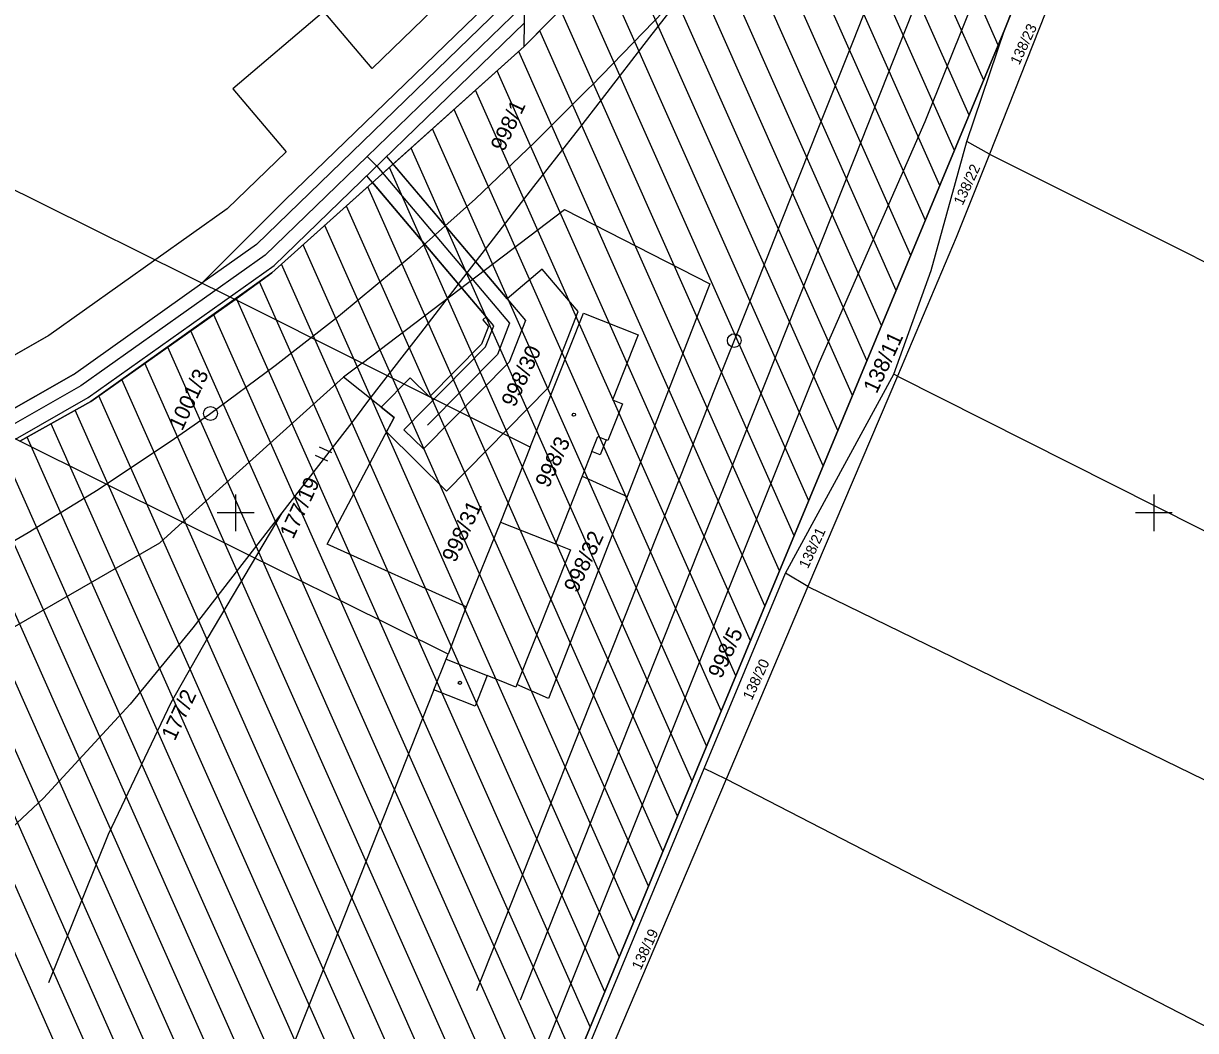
# Model space of a CAD drawing. Extents: x -755061 to -754557, y -1162352 to -1161657.
# Drawn here: x -754923.1 to -754795.5, y -1162256.4 to -1162146.7 of the extents above; entities that cross this region are included whole.
import ezdxf

# ---------------------------------------------------------------- set-up
doc = ezdxf.new("R2010")
doc.units = 0
for name, color, linetype in [('ADJ_Síť', 7, 'Continuous'), ('DTA-TZ', 7, 'Continuous'), ('DTA_DZ_DO_hranice', 7, 'Continuous'), ('DTA_DZ_DO_ostatní', 7, 'Continuous'), ('DTA_DZ_DO_ZPF', 7, 'Continuous'), ('DTA_ochranné pásmo', 7, 'Continuous'), ('DTA_projektovaný_stav', 7, 'Continuous'), ('DTA_správa_investora', 7, 'Continuous'), ('KN_Katastrální hranice', 7, 'Continuous'), ('KN_Vrstva 55', 7, 'Continuous'), ('KN_Vrstva 56', 7, 'Continuous'), ('KN_Vrstva 57', 7, 'Continuous'), ('KN_Vrstva 58', 7, 'Continuous'), ('KN_Vrstva 59', 7, 'Continuous'), ('Staniceni a namezniky', 7, 'Continuous'), ('Vrstva 1', 7, 'Continuous'), ('Vrstva 53', 7, 'Continuous')]:
    doc.layers.add(name, color=color, linetype=linetype)

msp = doc.modelspace()

# ---------------------------------------------------------------- linework, layer by layer
at = {"layer": 'ADJ_Síť'}
for points in [[(-754900, -1162198), (-754900, -1162200), (-754900, -1162202)], [(-754900, -1162198), (-754900, -1162200), (-754900, -1162202)], [(-754800, -1162198), (-754800, -1162200), (-754800, -1162202)], [(-754800, -1162198), (-754800, -1162200), (-754800, -1162202)], [(-754898, -1162200), (-754900, -1162200), (-754902, -1162200)], [(-754898, -1162200), (-754900, -1162200), (-754902, -1162200)], [(-754798, -1162200), (-754800, -1162200), (-754802, -1162200)], [(-754798, -1162200), (-754800, -1162200), (-754802, -1162200)]]:
    msp.add_lwpolyline(points, dxfattribs=at)
at = {"layer": 'DTA-TZ'}
msp.add_lwpolyline([(-754923.5, -1162192.2), (-754927.24, -1162190.37), (-754917.66, -1162184.92), (-754903.67, -1162174.98), (-754894.6, -1162165.92), (-754868.47, -1162140.62), (-754868.42, -1162135.23), (-754861.18, -1162138.93), (-754862.16, -1162142.69), (-754868.56, -1162149.23), (-754896.07, -1162173.88), (-754915.78, -1162187.87), (-754923.5, -1162192.2)], dxfattribs=at)
at = {"layer": 'DTA_DZ_DO_hranice'}
for points in [[(-754882.86, -1162162.04), (-754868.56, -1162149.23), (-754862.16, -1162142.69), (-754850.97, -1162130.01), (-754843.96, -1162120.41), (-754829.74, -1162126.8), (-754821.22, -1162106.53), (-754831.28, -1162101.48), (-754823.58, -1162088.63), (-754816.76, -1162075.96)], [(-754868.42, -1162135.23), (-754868.42, -1162135.42), (-754885.14, -1162151.61), (-754890.41, -1162145.41), (-754900.32, -1162153.82), (-754894.5, -1162160.68), (-754900.94, -1162166.91), (-754920.36, -1162180.69), (-754945.08, -1162194.78)], [(-754923.5, -1162192.2), (-754915.78, -1162187.87), (-754896.07, -1162173.88), (-754885.09, -1162164.04), (-754872.71, -1162178.65), (-754873.09, -1162178.98), (-754872.46, -1162179.71), (-754873.21, -1162181.63), (-754878.88, -1162187.38), (-754881.01, -1162185.28), (-754884.16, -1162188.47), (-754882.73, -1162189.61), (-754883.56, -1162191.19), (-754877.03, -1162197.62), (-754865.92, -1162186.35), (-754862.71, -1162178.08), (-754866.6, -1162173.48), (-754870.42, -1162176.71), (-754882.86, -1162162.04)]]:
    msp.add_lwpolyline(points, dxfattribs=at)
at = {"layer": 'DTA_DZ_DO_ostatní'}
msp.add_lwpolyline([(-754882.86, -1162162.04), (-754885.09, -1162164.04), (-754872.71, -1162178.65), (-754873.09, -1162178.98), (-754872.46, -1162179.71), (-754873.21, -1162181.63), (-754878.88, -1162187.38), (-754881.01, -1162185.28), (-754884.16, -1162188.47), (-754882.73, -1162189.61), (-754883.56, -1162191.19), (-754877.03, -1162197.62), (-754865.92, -1162186.35), (-754862.71, -1162178.08), (-754866.6, -1162173.48), (-754870.42, -1162176.71)], close=True, dxfattribs=at)
at = {"layer": 'DTA_DZ_DO_ZPF'}
msp.add_lwpolyline([(-754927.24, -1162190.37), (-754917.66, -1162184.92), (-754903.67, -1162174.98), (-754894.6, -1162165.92), (-754868.47, -1162140.62), (-754868.42, -1162135.42), (-754885.14, -1162151.61), (-754890.41, -1162145.41), (-754900.32, -1162153.82), (-754894.5, -1162160.68), (-754900.94, -1162166.91), (-754920.36, -1162180.69), (-754932.68, -1162187.72)], dxfattribs=at)
at = {"layer": 'DTA_ochranné pásmo'}
for p, q in [((-754868.49, -1162142.45), (-754897.74, -1162170.77)), ((-754895.81, -1162173.08), (-754868.53, -1162146.66)), ((-754897.74, -1162170.77), (-754903.67, -1162174.98)), ((-754916.05, -1162187.45), (-754895.81, -1162173.08)), ((-754917.66, -1162184.92), (-754903.67, -1162174.98)), ((-754917.66, -1162184.92), (-754927.24, -1162190.37)), ((-754917.66, -1162184.92), (-754917.66, -1162184.92)), ((-754923.98, -1162191.97), (-754916.05, -1162187.45))]:
    msp.add_line(p, q, dxfattribs=at)
msp.add_lwpolyline([(-754883.56, -1162161.21), (-754868.45, -1162179.04), (-754870.21, -1162183.57), (-754879.54, -1162193.04), (-754881.68, -1162190.94), (-754872.78, -1162181.91), (-754871.89, -1162179.62), (-754885.72, -1162163.3)], dxfattribs=at)
at = {"layer": 'DTA_projektovaný_stav'}
for points in [[(-754758.34, -1161933.06), (-754762.34, -1161937.68), (-754763.29, -1161936.85), (-754776.47, -1161949.62), (-754777.37, -1161978.41), (-754796.3, -1162026.28), (-754809.87, -1162057.58), (-754831.07, -1162091.65), (-754857.54, -1162133.93), (-754885.68, -1162161.18), (-754896.77, -1162171.93), (-754916.86, -1162186.18), (-754942.05, -1162200.54), (-754965.03, -1162211.64), (-754990.89, -1162220.78), (-755014.11, -1162227.27), (-755008.76, -1162253.14), (-755005.05, -1162256.17)], [(-754885.68, -1162161.18), (-754884.64, -1162162.26), (-754870.17, -1162179.33), (-754871.49, -1162182.74), (-754879.1, -1162190.46)]]:
    msp.add_lwpolyline(points, dxfattribs=at)
at = {"layer": 'DTA_správa_investora'}
for p, q in [((-754816.94, -1162149.08), (-754842.99, -1162090.44)), ((-754818.53, -1162152.9), (-754844.99, -1162093.32)), ((-754820.12, -1162156.71), (-754847, -1162096.19)), ((-754821.71, -1162160.53), (-754849, -1162099.07)), ((-754823.29, -1162164.34), (-754851.01, -1162101.94)), ((-754824.88, -1162168.15), (-754853.02, -1162104.82)), ((-754826.47, -1162171.97), (-754854.99, -1162107.76)), ((-754828.06, -1162175.78), (-754856.8, -1162111.07)), ((-754829.65, -1162179.6), (-754858.62, -1162114.36)), ((-754831.24, -1162183.41), (-754860.49, -1162117.55)), ((-754832.82, -1162187.23), (-754862.36, -1162120.73)), ((-754834.41, -1162191.04), (-754864.23, -1162123.91)), ((-754836, -1162194.86), (-754866.03, -1162127.25)), ((-754837.59, -1162198.67), (-754862.36, -1162142.9)), ((-754839.18, -1162202.48), (-754864.62, -1162145.2)), ((-754840.77, -1162206.3), (-754866.88, -1162147.51)), ((-754842.35, -1162210.11), (-754869.16, -1162149.77)), ((-754843.94, -1162213.93), (-754871.51, -1162151.87)), ((-754845.53, -1162217.74), (-754873.86, -1162153.97)), ((-754847.12, -1162221.56), (-754876.2, -1162156.08)), ((-754848.71, -1162225.37), (-754878.55, -1162158.18)), ((-754850.29, -1162229.19), (-754880.9, -1162160.29)), ((-754851.88, -1162233), (-754883.25, -1162162.39)), ((-754853.47, -1162236.83), (-754885.6, -1162164.49)), ((-754855.05, -1162240.65), (-754887.94, -1162166.6)), ((-754856.63, -1162244.48), (-754890.29, -1162168.7)), ((-754858.22, -1162248.3), (-754892.64, -1162170.81)), ((-754859.8, -1162252.13), (-754894.99, -1162172.91)), ((-754861.38, -1162255.95), (-754897.41, -1162174.85)), ((-754862.97, -1162259.78), (-754899.89, -1162176.65)), ((-754864.55, -1162263.6), (-754902.39, -1162178.42)), ((-754866.14, -1162267.42), (-754904.89, -1162180.18)), ((-754867.72, -1162271.25), (-754907.39, -1162181.94)), ((-754869.3, -1162275.07), (-754909.89, -1162183.71)), ((-754870.89, -1162278.9), (-754912.39, -1162185.47)), ((-754872.47, -1162282.72), (-754914.89, -1162187.24)), ((-754874.06, -1162286.55), (-754917.47, -1162188.82)), ((-754875.64, -1162290.37), (-754920.09, -1162190.29)), ((-754877.22, -1162294.2), (-754922.72, -1162191.76)), ((-754878.81, -1162298.02), (-754925.34, -1162193.26)), ((-754880.39, -1162301.85), (-754927.96, -1162194.76)), ((-754881.97, -1162305.67), (-754930.57, -1162196.26)), ((-754883.56, -1162309.49), (-754933.19, -1162197.76)), ((-754885.62, -1162312.24), (-754935.81, -1162199.26)), ((-754889.58, -1162310.72), (-754938.42, -1162200.76)), ((-754893.54, -1162309.19), (-754941.04, -1162202.26)), ((-754897.5, -1162307.67), (-754943.74, -1162203.57))]:
    msp.add_line(p, q, dxfattribs=at)
for points in [[(-755057.07, -1162235.3), (-755060.75, -1162244.84), (-754884.82, -1162312.55), (-754851.45, -1162231.96), (-754816.22, -1162147.35), (-754802.96, -1162113.9), (-754798.15, -1162101.07), (-754793.13, -1162087.4), (-754789, -1162076.26), (-754760.29, -1162004.33), (-754756.33, -1161996.85), (-754754.27, -1161988.55), (-754747.84, -1161978.77), (-754745.89, -1161978.47), (-754750.32, -1161972.64), (-754749.74, -1161970.12), (-754747.41, -1161959.83), (-754731.42, -1161979.09), (-754717.5, -1161955.11), (-754704.12, -1161932.06), (-754747.69, -1161915.3)], [(-754812.88, -1162068.75), (-754816.76, -1162075.96), (-754822.47, -1162073.13), (-754828.75, -1162070.02), (-754837.06, -1162081.94), (-754854.71, -1162107.25), (-754858.37, -1162113.93), (-754865.75, -1162126.5), (-754868.4, -1162133.56), (-754868.42, -1162135.23), (-754861.18, -1162138.93), (-754862.16, -1162142.69), (-754868.56, -1162149.23), (-754896.07, -1162173.88), (-754900.06, -1162176.77), (-754915.78, -1162187.87), (-754923.5, -1162192.2)]]:
    msp.add_lwpolyline(points, dxfattribs=at)
at = {"layer": 'KN_Katastrální hranice'}
msp.add_line((-754811.54, -1162135.54), (-754816.22, -1162147.35), dxfattribs=at)
msp.add_lwpolyline([(-754816.22, -1162147.35), (-754851.45, -1162231.96), (-754884.82, -1162312.55)], dxfattribs=at)
at = {"layer": 'KN_Vrstva 55'}
for p, q in [((-755012.97, -1162120.69), (-754900.06, -1162176.77)), ((-754868.56, -1162149.23), (-754868.42, -1162135.23)), ((-754811.54, -1162135.54), (-754816.22, -1162147.35)), ((-754811.54, -1162135.54), (-754816.22, -1162147.35)), ((-754808.43, -1162137.05), (-754817.91, -1162160.94)), ((-754868.56, -1162149.23), (-754862.16, -1162142.69)), ((-754820.38, -1162159.55), (-754816.22, -1162147.35)), ((-754817.91, -1162160.94), (-754820.38, -1162159.55)), ((-754886.23, -1162183.69), (-754864.19, -1162166.97)), ((-754886.23, -1162183.69), (-754900.06, -1162176.77)), ((-754886.23, -1162183.69), (-754888.26, -1162185.23)), ((-754867.91, -1162192.86), (-754886.23, -1162183.69)), ((-754888.26, -1162185.23), (-754905.78, -1162201)), ((-754840.13, -1162206.56), (-754828.31, -1162184.9)), ((-754827.93, -1162185.11), (-754837.67, -1162208.02)), ((-754827.93, -1162185.11), (-754828.31, -1162184.9)), ((-754905.78, -1162201), (-754923.5, -1162192.2)), ((-754862.27, -1162196.01), (-754857.37, -1162198.21)), ((-754876.85, -1162215.37), (-754905.78, -1162201)), ((-754848.96, -1162227.81), (-754840.13, -1162206.56)), ((-754837.67, -1162208.02), (-754840.13, -1162206.56)), ((-754837.67, -1162208.02), (-754846.58, -1162228.99)), ((-754874.91, -1162210.24), (-754876.85, -1162215.37)), ((-754863.44, -1162262.66), (-754848.96, -1162227.81)), ((-754846.58, -1162228.99), (-754848.96, -1162227.81))]:
    msp.add_line(p, q, dxfattribs=at)
for points in [[(-754888.68, -1162311.07), (-754870.17, -1162267.96), (-754836.4, -1162183.6), (-754824.89, -1162157.4), (-754808.97, -1162117.64), (-754790.52, -1162068.93), (-754761.32, -1161999.17), (-754754.27, -1161988.55)], [(-754816.22, -1162147.35), (-754851.45, -1162231.96), (-754884.82, -1162312.55)], [(-754816.22, -1162147.35), (-754851.45, -1162231.96), (-754884.82, -1162312.55)], [(-754900.06, -1162176.77), (-754896.07, -1162173.88), (-754868.56, -1162149.23)], [(-754828.31, -1162184.9), (-754824.25, -1162173.6), (-754820.38, -1162159.55)], [(-754817.91, -1162160.94), (-754821.51, -1162170), (-754827.93, -1162185.11)], [(-754817.91, -1162160.94), (-754773.06, -1162183.36), (-754728.03, -1162207.21)], [(-754864.19, -1162166.97), (-754848.34, -1162175.05), (-754857.37, -1162198.21)], [(-754923.5, -1162192.2), (-754915.78, -1162187.87), (-754900.06, -1162176.77)], [(-754867.91, -1162192.86), (-754862.1, -1162178.26), (-754856.15, -1162180.61), (-754858.96, -1162187.7), (-754857.88, -1162188.11), (-754859.46, -1162192.12), (-754859.66, -1162192.04), (-754860.31, -1162193.68), (-754861.2, -1162193.33), (-754862.27, -1162196.01)], [(-754874.91, -1162210.24), (-754890.05, -1162203.42), (-754882.73, -1162189.61), (-754888.26, -1162185.23)], [(-754827.93, -1162185.11), (-754743.71, -1162227.55), (-754737.2, -1162231.03)], [(-754867.91, -1162192.86), (-754871.15, -1162201.02), (-754874.91, -1162210.24)], [(-754862.27, -1162196.01), (-754865.18, -1162203.36), (-754863.54, -1162204.02), (-754869.36, -1162218.68)], [(-754857.37, -1162198.21), (-754865.94, -1162220.19), (-754869.36, -1162218.68)], [(-754971.15, -1162234.1), (-754958.95, -1162230.19), (-754951.07, -1162227.67), (-754947.14, -1162225.65), (-754943.74, -1162223.69), (-754908.27, -1162203.24), (-754905.78, -1162201)], [(-754837.67, -1162208.02), (-754745.6, -1162252.88)], [(-754878.41, -1162219.27), (-754877.09, -1162215.93), (-754876.85, -1162215.37)], [(-754869.36, -1162218.68), (-754869.47, -1162218.96), (-754872.61, -1162217.71), (-754873.93, -1162221.05), (-754878.41, -1162219.27)], [(-754878.41, -1162219.27), (-754890.63, -1162250.1), (-754895.21, -1162261.65), (-754899.8, -1162273.21), (-754904.37, -1162284.73), (-754908.92, -1162296.21), (-754911.35, -1162302.34)], [(-754846.58, -1162228.99), (-754858.59, -1162257.23), (-754861.29, -1162263.76)], [(-754754.65, -1162276.39), (-754846.58, -1162228.99)]]:
    msp.add_lwpolyline(points, dxfattribs=at)
at = {"layer": 'KN_Vrstva 56'}
for p, q in [((-754861.2, -1162193.33), (-754860.55, -1162191.69)), ((-754860.55, -1162191.69), (-754859.66, -1162192.04)), ((-754871.15, -1162201.02), (-754865.18, -1162203.36)), ((-754877.09, -1162215.93), (-754872.61, -1162217.71))]:
    msp.add_line(p, q, dxfattribs=at)
at = {"layer": 'KN_Vrstva 58'}
for p, q in [((-754889.52, -1162193.47), (-754890.88, -1162192.84)), ((-754889.95, -1162194.38), (-754891.3, -1162193.74))]:
    msp.add_line(p, q, dxfattribs=at)
at = {"layer": 'KN_Vrstva 59'}
for centre in [(-754863.16, -1162189.31), (-754875.58, -1162218.5)]:
    msp.add_circle(centre, 0.175, dxfattribs=at)
at = {"layer": 'Staniceni a namezniky'}
for centre in [(-754845.69, -1162181.24), (-754902.74, -1162189.18)]:
    msp.add_circle(centre, 0.75, dxfattribs=at)
at = {"layer": 'Vrstva 1'}
msp.add_line((-754885.52, -1162187.72), (-754886.99, -1162189.7), dxfattribs=at)
for points in [[(-754802.82, -1162068.46), (-754807.01, -1162076.73), (-754811.35, -1162084.87), (-754815.39, -1162092.12), (-754818.66, -1162097.67), (-754820.65, -1162100.99), (-754825.85, -1162109.19), (-754831.64, -1162117.68), (-754836.49, -1162124.37), (-754839.8, -1162128.71), (-754840.46, -1162129.57), (-754840.79, -1162129.99), (-754847.19, -1162138.25), (-754849.01, -1162140.58), (-754849.98, -1162141.84), (-754854.92, -1162148.19), (-754860.18, -1162155.01)], [(-754855.13, -1162205.06), (-754851.41, -1162195.67), (-754847.87, -1162186.72), (-754844.23, -1162177.57), (-754840.47, -1162168.07), (-754836.48, -1162158.01), (-754832.72, -1162148.55), (-754829.03, -1162139.24), (-754824.91, -1162128.83), (-754821.22, -1162119.52), (-754818.37, -1162112.34), (-754814.26, -1162101.97), (-754810.6, -1162092.76), (-754806.3, -1162081.9), (-754802.77, -1162073.01), (-754801.21, -1162069.06)], [(-754832.58, -1162161.33), (-754823.38, -1162138.13), (-754814.09, -1162114.62)], [(-754839.8, -1162128.71), (-754840.46, -1162129.57), (-754840.79, -1162129.99), (-754847.19, -1162138.25), (-754849.01, -1162140.58), (-754849.98, -1162141.84), (-754861.22, -1162153.45), (-754861.54, -1162153.77), (-754867.4, -1162159.65), (-754873.88, -1162165.79), (-754880.89, -1162172.03), (-754888.58, -1162178.44), (-754889.11, -1162178.86), (-754895.68, -1162183.99), (-754902.86, -1162189.27), (-754906.67, -1162191.94), (-754914.99, -1162197.47), (-754922.58, -1162202.18), (-754930.39, -1162206.7)], [(-754860.18, -1162155.01), (-754862.55, -1162158.06), (-754867.55, -1162164.48), (-754872.3, -1162170.63), (-754875.17, -1162174.35), (-754879.87, -1162180.43)], [(-754868.98, -1162253.01), (-754858.91, -1162227.64), (-754849.55, -1162204.07), (-754841.17, -1162182.97), (-754832.58, -1162161.33)], [(-754879.87, -1162180.43), (-754881.64, -1162182.7), (-754885.52, -1162187.72)], [(-754886.99, -1162189.7), (-754894.97, -1162200), (-754904.65, -1162212.5)], [(-754886.99, -1162189.7), (-754894.97, -1162200), (-754903.04, -1162213.58)], [(-754873.74, -1162251.98), (-754870.01, -1162242.56), (-754866.47, -1162233.66), (-754862.36, -1162223.3), (-754858.77, -1162214.24), (-754855.13, -1162205.06)], [(-754904.65, -1162212.5), (-754911.48, -1162220.81), (-754920.93, -1162231.04), (-754933.71, -1162243.01), (-754943.62, -1162251.86)], [(-754903.04, -1162213.58), (-754907.06, -1162220.68), (-754913.9, -1162235.02), (-754920.39, -1162251.15)]]:
    msp.add_lwpolyline(points, dxfattribs=at)
at = {"layer": 'Vrstva 53'}
for points in [[(-754884.82, -1162312.55), (-754851.45, -1162231.96), (-754816.22, -1162147.35), (-754802.96, -1162113.9), (-754798.15, -1162101.07), (-754793.13, -1162087.4), (-754789, -1162076.26), (-754760.29, -1162004.33), (-754756.33, -1161996.85), (-754754.27, -1161988.55), (-754747.84, -1161978.77), (-754745.89, -1161978.47), (-754750.32, -1161972.64), (-754749.74, -1161970.12), (-754747.41, -1161959.83), (-754731.42, -1161979.09), (-754717.5, -1161955.11), (-754704.12, -1161932.06)], [(-754812.88, -1162068.75), (-754816.76, -1162075.96), (-754822.47, -1162073.13), (-754828.75, -1162070.02), (-754837.06, -1162081.94), (-754854.71, -1162107.25), (-754858.37, -1162113.93), (-754865.75, -1162126.5), (-754868.4, -1162133.56), (-754868.42, -1162135.23), (-754861.18, -1162138.93), (-754862.16, -1162142.69), (-754868.56, -1162149.23), (-754896.07, -1162173.88), (-754900.06, -1162176.77), (-754915.78, -1162187.87), (-754923.5, -1162192.2)]]:
    msp.add_lwpolyline(points, dxfattribs=at)

# ---------------------------------------------------------------- texts
at = {"layer": 'KN_Vrstva 57'}
for s, height, p in [('138/23', 1.139, (-754814.66, -1162151.31)), ('998/1', 1.7, (-754870.78, -1162160.74)), ('138/22', 1.139, (-754820.83, -1162166.6)), ('138/11', 1.7, (-754830.19, -1162187.1)), ('998/30', 1.7, (-754869.61, -1162188.59)), ('1001/3', 1.7, (-754905.83, -1162191.15)), ('998/3', 1.7, (-754865.92, -1162197.37)), ('177/19', 1.7, (-754893.74, -1162202.93)), ('998/31', 1.7, (-754876.08, -1162205.5)), ('998/32', 1.7, (-754862.8, -1162208.8)), ('138/21', 1.139, (-754837.68, -1162206.16)), ('998/5', 1.7, (-754847.11, -1162218.14)), ('138/20', 1.139, (-754843.79, -1162220.47)), ('177/2', 1.7, (-754906.63, -1162224.9)), ('138/19', 1.139, (-754855.89, -1162249.86))]:
    msp.add_text(s, height=height, rotation=65, dxfattribs=at).set_placement(p)

doc.saveas('drawing.dxf')
